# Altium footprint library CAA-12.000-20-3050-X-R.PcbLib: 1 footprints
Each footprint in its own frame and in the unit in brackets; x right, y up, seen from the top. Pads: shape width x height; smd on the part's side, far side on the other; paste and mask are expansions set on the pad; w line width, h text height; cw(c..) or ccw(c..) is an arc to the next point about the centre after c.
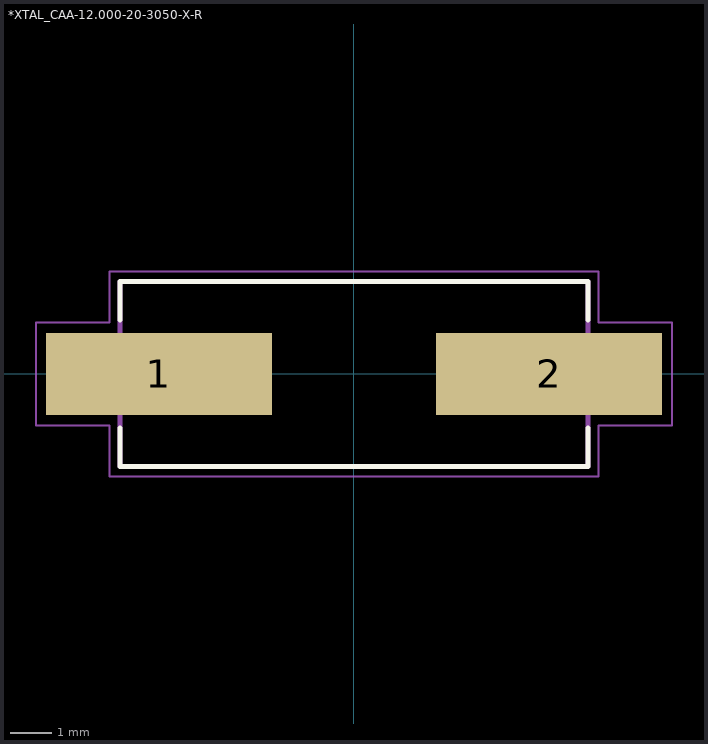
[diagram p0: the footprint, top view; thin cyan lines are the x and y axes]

## *XTAL_CAA-12.000-20-3050-X-R [mm]
pads (2):
  rect 5.5x2 smd: 1(-4.75,0) 2(4.75,0)
Top Overlay:
  lines w0.127: -5.7,-1.32 -5.7,-2.25 5.7,-2.25 5.7,-1.32 ; -5.7,1.32 -5.7,2.25 5.7,2.25 5.7,1.32
Mechanical 4:
  lines w0.127: -5.7,-2.25 5.7,-2.25 ; -5.7,-2.25 -5.7,2.25 ; -5.7,-2.25 5.7,-2.25 ; -5.7,-2.25 -5.7,2.25 ; -5.7,2.25 5.7,2.25 ; -5.7,2.25 5.7,2.25 ; 5.7,-2.25 5.7,2.25 ; 5.7,-2.25 5.7,2.25
Mechanical 16:
  lines w0.05: -7.75,-1.25 -5.95,-1.25 -5.95,-2.5 5.95,-2.5 5.95,-1.25 7.75,-1.25 7.75,1.25 5.95,1.25 5.95,2.5 -5.95,2.5 -5.95,1.25 -7.75,1.25 -7.75,-1.25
